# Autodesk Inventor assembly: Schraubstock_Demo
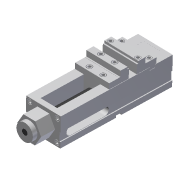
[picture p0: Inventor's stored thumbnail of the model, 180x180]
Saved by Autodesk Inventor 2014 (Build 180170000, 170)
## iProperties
Company: VDW-Nachwuchsstiftung
Created: 2014-03
Part Number: Schraubstock_Demo
Document SubType Name: Assembly
Designer: e_dammj
Sending System: SolidWorks 2011
Last Author: e_boekem
Author: e_dammj
Title: Schaubstock
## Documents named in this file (5)
- C:\Users\e_dammj\Documents\03_Schulungsunterlagen\Schulungsunterlagen in Bearbeitung\Inventor\Übungsteile_Inventorunterlage\INVEMTOR_CAM\Schraubstock_Demo\03_IAM\Schraubstock_Demo.iam
- C:\Users\e_dammj\Documents\03_Schulungsunterlagen\Schulungsunterlagen in Bearbeitung\Inventor\Übungsteile_Inventorunterlage\INVEMTOR_CAM\Schraubstock_Demo\01_IPT\Backe20x40.ipt
- C:\Users\e_dammj\Documents\03_Schulungsunterlagen\Schulungsunterlagen in Bearbeitung\Inventor\Übungsteile_Inventorunterlage\INVEMTOR_CAM\Schraubstock_Demo\01_IPT\Unterteil.ipt
- C:\Users\e_dammj\Documents\03_Schulungsunterlagen\Schulungsunterlagen in Bearbeitung\Inventor\Übungsteile_Inventorunterlage\INVEMTOR_CAM\Schraubstock_Demo\01_IPT\Backe 40 x 20 ohne.ipt
- C:\Users\e_dammj\Documents\03_Schulungsunterlagen\Schulungsunterlagen in Bearbeitung\Inventor\Übungsteile_Inventorunterlage\INVEMTOR_CAM\Schraubstock_Demo\01_IPT\Spindel.ipt
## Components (4 placed, 4 different names)
1. Unterteil:1 — Passend:1, Fluchtend:1, Passend:2, Passend:4, Passend:5, Planar:1
2. Backe20x40:1 — Passend:1, Fluchtend:1, Passend:2, Passend:6
3. Backe 40 x 20 ohne:1 — Passend:3, Planar:1, Passend:6
4. Spindel:2 — Passend:3, Passend:4, Passend:5
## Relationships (8: Mate 6, Flush 1, PlanarJoint 1)
- Passend:1 [Mate]: Unterteil:1 ↔ Backe20x40:1
- Fluchtend:1 [Flush]: Unterteil:1 ↔ Backe20x40:1
- Passend:2 [Mate]: Unterteil:1 ↔ Backe20x40:1
- Passend:3 [Mate]: Backe 40 x 20 ohne:1 ↔ Spindel:2
- Passend:4 [Mate]: Unterteil:1 ↔ Spindel:2
- Passend:5 [Mate]: Unterteil:1 ↔ Spindel:2
- Planar:1: Unterteil:1 ↔ Backe 40 x 20 ohne:1
- Passend:6 [Mate]: Backe20x40:1 ↔ Backe 40 x 20 ohne:1
